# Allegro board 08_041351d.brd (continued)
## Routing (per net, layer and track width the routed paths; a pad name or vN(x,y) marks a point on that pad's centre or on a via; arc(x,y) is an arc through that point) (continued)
PS_MIO06_500_QSPI0_SCLK: length 51.3
  TOP w0.127: U1.A5 v1(37.14,35.39)
  TOP w0.14: v1(60.63,57.64) 60.63,58.66 61.27,59.29 67.74,59.29 68.12,58.91 68.12,58.15 68.62,57.66 U13.B2
  L3_SIGNAL w0.095: v1(37.14,35.39) 37.49,35.39 37.8,35.69 37.8,38.41 40.64,41.26 40.64,45.78 42,47.13 48.97,47.13 48.98,47.12 50.65,47.12 51.18,47.66 54.92,47.66 60.63,53.37 v1(60.63,57.64)
  BOTTOM w0.14: R116.1 v1(60.63,57.64)
PS_MIO07_500_USB_RESET_B: length 32.4
  TOP w0.127: U1.D8 v1(34.74,32.99)
  TOP w0.14: U15.27 v1(22.16,49.4)
  L6_SIGNAL w0.095: v1(22.16,49.4) 22.15,49.38 22.15,40.88 20.25,38.97 20.25,35.67 v1(20.5,35.41)
  L15_SIGNAL w0.095: v1(34.74,32.99) 34.74,32.99 34.34,33.38 26.53,33.38 26.34,33.57 26.34,33.95 26.09,34.21 22.51,34.21 22.27,34.45 22.27,34.73 22.08,34.93 20.99,34.93 v1(20.5,35.41)
  BOTTOM w0.14: R31.2 34.81,33.06 v1(34.74,32.99)
PS_MIO08_500_ETH0_RESETN: length 43.8
  TOP w0.127: U1.D5 v1(34.74,35.39)
  L16_SIGNAL w0.095: v1(16.05,3.66) 16.05,6.14 17.2,8.36 18.98,12.43 20.5,15.09 25.58,20.17 25.58,20.81 27.1,22.33 27.1,29.06 27.49,29.45 27.68,29.45 27.87,29.65 27.87,29.84 29.89,31.85 30.08,31.85 30.28,32.05 30.28,32.24 30.69,32.65 30.88,32.65 31.07,32.85 31.07,33.04 31.49,33.45 32.19,33.45 32.48,33.45 32.8,33.77 32.8,33.93 33.12,34.25 33.28,34.25 33.47,34.45 33.47,34.61 33.79,34.93 34.27,34.93 v1(34.74,35.39)
  BOTTOM w0.14: v1(16.05,3.66) 16.73,4.34 U10.16 ; R32.2 35.12,35 v1(34.74,35.39)
PS_MIO09_500_USB_CLK_PD: length 39.1
  TOP w0.127: v1(36.34,35.39) U1.B5
  TOP w0.14: R27.1 16.98,59.46 Y3.1 16.98,57.98 v1(17.83,57.13)
  L6_SIGNAL w0.095: v1(25.96,45.7) 23.67,47.99 23.67,49.31 24,49.64 24,50.53 21.9,52.63 21.9,54.59 19.36,57.13 v1(17.83,57.13)
  BOTTOM w0.14: v1(25.96,45.7) 33.33,45.7 35.1,43.92 35.87,43.92 36.25,43.54 36.25,42.53 36.76,42.02 36.76,35.8 36.35,35.39 v1(36.34,35.39)
PS_MIO10_500_JX4: length 67.2
  TOP w0.127: U1.E9 v1(33.94,32.19)
  L15_SIGNAL w0.095: v1(33.94,32.19) 34.01,32.19 34.34,31.86 34.34,31.1 35.23,30.21 39.93,30.21 42.22,27.92 45.77,27.92 47.33,26.36 49.81,26.36 51.49,24.68 51.49,20.81 54.73,17.57 55.87,17.57 56.44,17 59.3,17 62.79,13.51 66.92,13.51 67.49,12.94 73.71,12.94 73.97,13.19 73.97,15.09 74.6,15.73 76.19,15.73 76.82,16.36 81.18,16.36 82.75,14.79 v1(83.21,14.79)
  BOTTOM w0.14: v1(83.21,14.79) 83.87,15.45 84.33,15.45 84.66,15.78 84.66,16.04 84.79,16.17 JX4.87
PS_MIO11_500_JX4: length 60.6
  TOP w0.127: U1.C6 v1(35.54,34.59)
  L15_SIGNAL w0.095: v1(35.54,34.59) 35.55,34.59 35.99,35.03 37.26,35.03 39.42,32.87 40.69,32.87 40.95,32.62 49.3,32.62 50.66,31.26 50.66,30.21 51.55,29.32 51.55,27.67 53.07,26.14 53.46,26.14 54.66,24.94 54.66,23.92 58.6,19.98 61.39,19.98 63.36,18.02 66.35,18.02 67.24,18.9 80.76,18.9 v1(82.98,16.68)
  BOTTOM w0.14: v1(82.98,16.68) 82.98,16.3 82.85,16.17 JX4.88
PS_MIO12_500_JX4: length 58.8
  TOP w0.127: U1.D9 v1(34.74,32.19)
  L15_SIGNAL w0.095: v1(34.74,32.19) 34.74,32.1 35.11,31.73 36.48,31.73 36.8,31.41 36.8,31.25 36.99,31.05 37.06,31.05 37.64,30.46 40.57,30.46 42.22,28.81 45.77,28.81 47.42,27.16 49.46,27.16 51.8,24.81 51.8,22.33 53.07,21.06 54.6,21.06 55.42,20.24 55.42,18.59 56.63,17.38 59.43,17.38 62.98,13.82 71.17,13.82 73.39,16.05 75.74,16.05 v1(76.19,16.49)
  BOTTOM w0.14: v1(76.19,16.49) 79.68,16.49 80.16,16.97 JX4.86
PS_MIO13_500_JX4: length 64.6
  TOP w0.127: U1.E8 v1(33.94,32.99)
  L15_SIGNAL w0.095: v1(33.94,32.99) 33.97,32.99 34.34,32.62 38.03,32.62 39.74,30.91 40.75,30.91 41.23,30.43 48.98,30.43 49.2,30.21 49.2,29.76 49.39,29.57 49.84,29.57 50.47,28.94 50.47,27.16 52.44,25.19 52.44,22.58 53.25,21.78 54.9,21.78 56.14,20.54 56.14,18.88 56.93,18.1 59.72,18.1 60.95,16.87 64.48,16.87 65.25,16.11 69.01,16.11 69.78,16.87 81.13,16.87 82.78,15.22 83.64,15.22 v1(84.08,14.79)
  BOTTOM w0.14: v1(84.08,14.79) 84.29,14.57 JX4.91
PS_MIO14_500_JX4: length 67.2
  TOP w0.127: U1.C5 v1(35.54,35.39)
  L15_SIGNAL w0.095: v1(87.38,14.56) 85.9,16.03 85.9,19.29 81.97,23.22 80,23.22 79.49,23.73 57.08,23.73 54.34,26.46 53.2,26.46 51.87,27.79 51.87,29.45 50.98,30.33 50.98,31.46 49.33,33.11 48.68,33.11 48.67,33.13 40.18,33.13 39.17,34.14 39.17,34.4 37.77,35.8 35.87,35.8 35.54,35.46 v1(35.54,35.39)
  BOTTOM w0.14: JX4.93 87.15,13.77 87.38,14 v1(87.38,14.56)
PS_MIO15_500_JX4: length 63.1
  TOP w0.127: U1.C8 v1(35.54,32.99)
  L15_SIGNAL w0.095: v1(35.54,32.99) 35.6,32.99 35.99,33.38 37.77,33.38 39.87,31.29 49.58,31.29 50.03,30.84 50.03,29.89 50.85,29.06 50.85,27.35 52.76,25.44 52.76,22.71 53.33,22.14 55.42,22.14 58.31,19.25 59.08,19.25 61.08,17.25 64.82,17.25 65.58,16.49 68.63,16.49 69.39,17.25 81.21,17.25 82.83,15.63 v1(83.21,15.63)
  BOTTOM w0.14: JX4.85 84.78,16.97 84.63,16.82 84.63,16.44 84.1,15.91 83.49,15.91 v1(83.21,15.63)
PS_MIO16_501_ETH0_TX_CLK: length 43
  TOP w0.127: U1.A19 v1(37.14,23.39)
  L16_SIGNAL w0.095: v1(37.14,23.39) 37.52,23.01 37.52,21.44 36.63,20.56 36.63,20.05 36.37,19.79 36.37,18.02 36.5,17.89 36.88,17.89 37.01,17.76 37.01,17.51 36.88,17.38 36.5,17.38 36.37,17.25 36.37,16.62 36.12,16.36 34.6,16.36 34.47,16.49 33.58,16.49 33.45,16.36 33.45,15.98 33.58,15.86 34.85,15.86 34.98,15.73 34.98,15.22 34.72,14.97 34.72,11.79 35.61,10.9 35.61,8.11 35.36,7.86 33.71,7.86 33.45,8.11 33.45,8.74 33.33,8.87 33.2,8.87 33.07,8.74 33.07,7.6 33.33,7.35 33.45,7.35 33.71,7.09 33.71,6.71 33.45,6.46 31.68,6.46 31.42,6.71 31.42,8.49 31.29,8.62 30.91,8.62 30.79,8.74 30.79,10.01 30.66,10.14 30.41,10.14 30.15,9.89 30.15,8.36 29.39,7.6 v1(29.39,7.35)
  BOTTOM w0.14: v1(29.39,7.35) 29.39,6.97 28.73,6.31 27.69,6.31 27.45,6.07 27.45,5.78 27.27,5.59 26.11,5.59 25.86,5.34 U10.53
PS_MIO17_501_ETH0_TX_D0: length 41.9
  TOP w0.127: U1.E14 v1(33.94,27.39)
  L16_SIGNAL w0.095: v1(26.82,6.84) 26.24,6.84 26.09,6.99 26.09,10.01 26.9,10.83 27.47,10.83 28.16,11.52 28.16,11.55 28.26,11.65 28.26,11.93 28.75,12.43 30.66,12.43 30.79,12.3 30.79,11.28 30.91,11.16 31.17,11.16 31.29,11.28 31.29,12.05 31.42,12.17 31.8,12.17 31.93,12.05 31.93,11.28 32.06,11.16 32.44,11.16 32.56,11.28 32.56,11.54 32.69,11.67 32.95,11.67 33.07,11.54 33.07,11.28 33.2,11.16 33.45,11.16 33.71,11.41 33.71,12.17 33.58,12.3 32.31,12.3 32.18,12.43 32.18,12.68 32.31,12.81 33.2,12.81 33.45,13.06 33.58,13.06 33.71,13.19 33.71,13.7 33.45,13.95 30.91,13.95 30.41,14.46 30.41,14.97 32.99,17.55 33.75,17.55 34.47,18.27 34.47,20.33 34.38,20.41 34.38,26.94 v1(33.94,27.39)
  BOTTOM w0.14: v1(26.82,6.84) 26.82,6.84 U10.50
PS_MIO18_501_ETH0_TX_D1: length 42
  TOP w0.127: U1.B18 v1(36.34,24.19)
  L16_SIGNAL w0.095: v1(36.34,24.19) 36.32,24.19 35.99,23.86 35.99,22.12 35.07,21.2 35.07,20.43 34.98,20.33 34.98,18.27 33.96,17.25 33.07,17.25 31.29,15.48 31.29,14.46 31.55,14.21 33.58,14.21 34.09,13.7 34.09,11.28 33.71,10.9 33.58,10.9 33.33,10.65 33.33,10.27 33.07,10.01 32.31,10.01 32.06,10.27 32.06,10.65 31.8,10.9 30.41,10.9 30.28,11.03 30.28,11.41 29.9,11.79 29.01,11.79 28.84,11.62 28.84,11.27 28.64,11.07 28.08,11.07 27.65,10.65 27.61,10.65 27.56,10.61 27.06,10.61 26.31,9.86 26.31,9.6 26.56,9.35 27.1,9.35 27.36,9.09 27.36,8.65 27.1,8.4 26.55,8.4 26.34,8.19 26.34,7.89 26.55,7.69 27.91,7.69 28.25,7.35 28.25,6.84 28.5,6.59 28.5,4.81 28.25,4.55 27.74,4.55 27.48,4.81 27.48,6.22 27.36,6.34 v1(26.98,6.34)
  BOTTOM w0.14: v1(26.98,6.34) U10.51
PS_MIO19_501_ETH0_TX_D2: length 43.9
  TOP w0.127: U1.D10 v1(34.74,31.39)
  L16_SIGNAL w0.095: v1(34.74,31.39) 35.87,30.26 35.87,29.94 35.87,29.93 35.87,29.65 35.67,29.45 35.45,29.45 35.2,29.19 35.2,27.18 35.45,26.93 35.68,26.93 35.87,26.73 35.87,26.52 36.15,26.25 36.52,26.25 36.76,26.02 36.76,24.87 37.01,24.62 37.26,24.62 37.77,24.11 37.77,21.32 37.39,20.94 37.39,17.25 34.98,14.84 34.98,11.92 35.87,11.03 35.87,7.98 33.58,5.7 33.58,5.44 33.33,5.19 32.69,5.19 32.44,5.44 31.17,5.44 31.04,5.57 31.04,7.98 30.79,8.24 30.53,8.24 29.9,7.6 v1(29.9,7.35)
  BOTTOM w0.14: U10.54 25.87,4.84 26.35,5.32 28.12,5.32 29.75,6.95 29.75,7.2 v1(29.9,7.35)
PS_MIO20_501_ETH0_TX_D3: length 42.6
  TOP w0.127: U1.A17 v1(37.14,24.99)
  L16_SIGNAL w0.095: v1(30.41,7.35) 30.41,6.97 29.14,5.7 29.14,4.43 28.88,4.17 28.25,4.17 27.99,3.92 27.99,3.66 28.25,3.41 33.45,3.41 33.96,3.92 33.96,4.93 34.47,5.44 34.98,5.44 36.12,6.59 36.12,11.16 35.23,12.05 35.23,14.71 37.64,17.13 37.64,20.81 38.28,21.44 38.28,24.11 37.4,24.99 v1(37.14,24.99)
  BOTTOM w0.14: v1(30.41,7.35) 30.26,7.2 30.26,7.08 28.23,5.06 26.59,5.06 25.88,4.34 U10.55
PS_MIO21_501_ETH0_TX_CTL: length 41.8
  TOP w0.127: v1(33.14,27.39) U1.F14
  L16_SIGNAL w0.095: v1(33.14,27.39) 32.8,27.05 32.8,19.54 32.56,19.31 32.56,18.9 32.8,18.67 32.8,18.37 31.68,17.25 30.66,17.25 30.53,17.13 30.53,16.11 29.26,14.84 27.74,14.84 27.61,14.71 27.61,14.33 27.74,14.21 30.28,14.21 30.79,13.7 33.07,13.7 33.2,13.57 33.2,13.32 33.07,13.19 31.93,13.19 31.8,13.06 31.8,12.68 31.68,12.55 31.04,12.55 30.91,12.68 30.91,13.06 30.79,13.19 28.37,13.19 28.25,13.06 28.25,12.43 27.99,12.17 27.99,11.7 27.94,11.64 27.94,11.61 27.56,11.23 26.41,11.23 25.83,10.65 25.83,5.32 v1(26.72,4.43)
  BOTTOM w0.14: U10.56 26.14,3.84 v1(26.72,4.43)
PS_MIO22_501_ETH0_RX_CLK: length 42.9
  TOP w0.127: U1.B17 35.94,25.38 36.33,24.99 v1(36.34,24.99)
  L16_SIGNAL w0.095: v1(27.01,10.01) 27.01,10.09 27.27,10.35 27.7,10.35 28.19,10.85 28.37,10.85 28.5,10.72 28.5,10.4 28.63,10.27 29.01,10.27 29.14,10.4 29.14,11.03 29.26,11.16 29.52,11.16 29.64,11.03 29.64,10.4 29.77,10.27 30.02,10.27 30.28,10.52 31.04,10.52 31.17,10.4 31.17,9.13 31.29,9 31.68,9 31.8,8.87 31.8,7.73 32.06,7.47 32.56,7.47 32.82,7.73 32.82,9.13 33.07,9.38 33.45,9.38 33.71,9.13 33.71,8.49 34.09,8.11 35.1,8.11 35.36,8.36 35.36,10.52 35.23,10.65 34.98,10.65 34.85,10.52 34.85,9.89 34.72,9.76 34.47,9.76 34.34,9.89 34.34,13.95 33.71,14.59 32.28,14.59 32.27,14.57 31.82,14.57 31.68,14.71 31.68,15.22 33.38,16.93 34.4,16.93 35.99,18.52 35.99,20.33 35.91,20.41 35.91,21.23 36.76,22.08 36.76,24.37 36.34,24.79 v1(36.34,24.99)
  BOTTOM w0.14: U10.46 25.93,8.84 26.87,9.78 26.87,9.78 27.01,9.92 v1(27.01,10.01)
PS_MIO23_501_ETH0_RX_D0: length 42.3
  TOP w0.127: U1.D11 v1(34.74,29.79)
  L16_SIGNAL w0.095: v1(26.85,11.79) 26.85,13.57 26.37,14.05 26.37,14.21 26.43,14.27 26.43,14.6 26.23,14.8 26.21,14.8 26.21,15.73 26.34,15.86 26.72,15.86 26.95,16.09 27.27,16.09 27.51,16.32 27.51,16.64 28.63,17.76 29.01,17.76 29.77,18.52 30.28,18.52 30.41,18.65 30.41,19.29 30.28,19.41 29.9,19.41 29.77,19.54 29.77,20.05 29.9,20.17 31.17,20.17 31.29,20.3 31.29,21.06 31.17,21.19 29.64,21.19 29.52,21.32 29.52,26.91 29.64,27.03 30.15,27.03 30.28,26.91 30.28,21.95 30.41,21.83 31.04,21.83 31.17,21.95 31.17,28.3 31.51,28.65 31.68,28.65 31.87,28.85 31.87,29.01 32.19,29.33 33.21,29.33 33.71,29.83 34.7,29.83 v1(34.74,29.79)
  BOTTOM w0.14: U10.44 25.92,9.84 26.21,10.14 26.21,10.4 26.85,11.03 v1(26.85,11.79)
PS_MIO24_501_ETH0_RX_D1: length 42
  TOP w0.127: U1.A16 v1(37.14,25.79)
  L16_SIGNAL w0.095: v1(35.87,14.21) 37.9,16.24 37.9,20.56 38.66,21.32 38.66,24.24 37.14,25.76 v1(37.14,25.79)
  BOTTOM w0.14: v1(35.87,14.21) 35.87,13.82 35.74,13.7 33.83,13.7 33.58,13.95 33.58,14.46 33.83,14.71 34.98,14.71 35.23,14.97 35.23,15.86 34.98,16.11 34.47,16.11 33.96,16.62 32.06,16.62 31.55,16.11 28.37,16.11 28.18,16.3 27.54,16.3 27.29,16.05 27.29,15.98 27.04,15.73 26.74,15.73 26.49,15.48 26.49,14.59 26.74,14.33 27.48,14.33 27.74,14.59 27.74,15.35 27.99,15.6 28.37,15.6 28.63,15.35 28.63,13.57 28.37,13.32 27.48,13.32 27.23,13.06 27.23,10.9 26.6,10.27 26.6,9.89 26.05,9.34 U10.45
PS_MIO25_501_ETH0_RX_D2: length 43.9
  TOP w0.127: v1(33.14,26.59) U1.F15
  L16_SIGNAL w0.095: v1(33.14,26.59) 33.58,26.14 33.58,20.05 33.33,19.79 33.33,18.52 29.9,15.09 v1(29.9,14.59)
  BOTTOM w0.14: U10.47 26.07,8.34 27.38,9.65 27.68,9.65 28.53,10.5 29.04,10.5 30.02,9.51 30.02,8.49 30.28,8.24 31.17,8.24 31.55,7.86 32.64,7.86 32.89,8.11 32.89,8.8 32.56,9.13 31.04,9.13 30.41,9.76 30.41,10.27 29.9,10.78 29.46,10.78 29.14,11.1 29.14,14.71 29.77,15.35 30.91,15.35 31.77,14.5 31.77,13.57 32.02,13.32 32.31,13.32 32.56,13.06 32.56,12.55 32.31,12.3 31.17,12.3 30.91,12.55 30.91,13.32 30.66,13.57 30.15,13.57 29.9,13.82 v1(29.9,14.59)
PS_MIO26_501_ETH0_RX_D3: length 41.9
  TOP w0.127: U1.A15 v1(37.14,26.59)
  L16_SIGNAL w0.095: v1(24.82,7.84) 24.82,4.81 25.45,4.17 25.45,2.9 25.79,2.56 33.62,2.56 34.98,3.92 34.98,5.06 36.37,6.46 36.37,14.08 38.41,16.11 38.41,17.89 38.79,18.27 38.79,20.68 39.04,20.94 39.04,24.68 v1(37.14,26.59)
  BOTTOM w0.14: U10.48 v1(24.82,7.84)
PS_MIO27_501_ETH0_RX_CTL: length 41.8
  TOP w0.127: U1.D13 v1(34.74,28.19)
  L16_SIGNAL w0.095: v1(34.74,28.19) 34.34,28.58 34.34,29.32 34.09,29.57 33.83,29.57 33.58,29.32 33.58,27.92 33.45,27.79 32.82,27.79 32.69,27.92 32.69,28.3 32.67,28.32 32.67,28.33 32.48,28.53 32.47,28.53 32.44,28.56 32.18,28.56 31.93,28.3 31.93,21.44 32.18,21.19 32.18,20.3 31.8,19.92 31.8,17.89 31.55,17.63 29.9,17.63 29.64,17.38 29.01,17.38 28.88,17.25 28.88,16.49 29.01,16.36 29.64,16.36 29.77,16.24 29.77,16.11 29.64,15.98 27.48,15.98 27.36,15.87 27.24,15.87 27.23,15.86 27.23,15.6 27.36,15.48 29.14,15.48 29.26,15.35 29.26,15.22 29.14,15.09 27.1,15.09 26.98,14.97 26.98,13.95 27.1,13.82 30.02,13.82 30.15,13.7 30.15,13.57 30.02,13.44 27.52,13.44 27.27,13.19 27.27,11.69 27.03,11.45 26.68,11.45 v1(26.34,11.79)
  BOTTOM w0.14: v1(26.34,11.79) 26.34,11.53 25.59,10.78 U10.43
PS_MIO28_501_USB0_D4: length 38.6
  TOP w0.127: U1.C16 v1(35.54,25.79)
  TOP w0.14: v1(26.85,54.97) 26.07,54.19 U15.7
  L6_SIGNAL w0.095: v1(35.54,25.79) 35.07,26.25 35.07,26.73 34.88,26.93 33.12,26.93 32.8,27.25 32.8,27.41 32.48,27.73 32.32,27.73 31.87,28.17 31.87,28.33 31.68,28.53 31.52,28.53 31.2,28.85 31.2,29.04 30.78,29.45 30.59,29.45 30.4,29.65 30.4,29.84 29.37,30.86 29.37,31.62 29.14,31.86 29.14,41.26 28.75,41.64 28.75,48.77 26.98,50.55 26.98,52.08 26.51,52.55 26.51,53.41 26.42,53.5 26.42,53.93 26.65,54.16 27.61,54.16 27.79,54.33 27.79,54.47 27.64,54.62 26.95,54.62 26.87,54.69 26.87,54.95 v1(26.85,54.97)
PS_MIO29_501_USB0_DIR: length 32.9
  TOP w0.127: U1.C13 v1(35.54,28.19)
  TOP w0.14: U15.31 24.16,49.53 v1(24.31,49.38)
  BOTTOM w0.14: v1(24.31,49.38) 24.82,49.38 25.2,49 25.2,45.7 24.69,45.19 24.69,44.3 25.2,43.8 25.2,39.1 25.57,38.72 25.57,38.44 25.79,38.23 26.07,38.23 26.37,37.92 26.37,37.64 26.59,37.43 26.87,37.43 27.17,37.12 27.17,36.84 27.39,36.63 27.67,36.63 27.97,36.32 27.97,36.04 28.19,35.83 28.47,35.83 29.26,35.03 29.26,28.3 29.77,27.79 35.1,27.79 35.5,28.19 v1(35.54,28.19)
PS_MIO30_501_USB0_STP: length 34.7
  TOP w0.127: U1.C15 v1(35.54,26.59)
  TOP w0.14: U15.29 v1(23.16,49.39)
  BOTTOM w0.14: v1(23.16,49.39) 23.17,49.38 23.17,45.7 22.79,45.32 22.79,40.49 24.33,38.95 24.49,38.95 24.7,38.74 24.7,38.52 24.99,38.23 25.21,38.23 25.5,37.94 25.5,37.72 25.79,37.43 26.01,37.43 26.3,37.14 26.3,36.92 26.59,36.63 26.81,36.63 27.1,36.34 27.1,36.12 27.39,35.83 27.61,35.83 27.9,35.54 27.9,35.32 28.19,35.03 28.25,35.03 28.88,34.4 28.88,26.78 29.43,26.23 35.19,26.23 35.54,26.57 v1(35.54,26.59)
PS_MIO31_501_USB0_NXT: length 35.3
  TOP w0.127: U1.E16 v1(33.94,25.79)
  TOP w0.14: U15.2 v1(25.94,51.69)
  L6_SIGNAL w0.095: v1(25.94,51.69) 26.47,51.16 26.47,49.38 26.8,49.05 26.8,48.83 26.88,48.75 27.48,48.75 27.61,48.62 27.61,48.24 27.48,48.11 26.85,48.11 26.8,48.06 26.8,47.7 26.89,47.61 27.48,47.61 27.61,47.48 27.61,47.1 27.48,46.97 26.98,46.97 26.8,46.79 26.8,44.61 27.7,43.71 27.7,39.14 28,38.84 28,35.25 28.48,34.77 28.48,34.41 28,33.93 28,32.05 28.19,31.85 28.35,31.85 28.66,31.54 28.66,31.51 28.91,31.26 28.91,30.33 29.37,29.87 29.37,29.56 29.6,29.33 29.6,28.85 29.79,28.65 30.08,28.65 30.4,28.33 30.4,28.05 30.59,27.85 30.88,27.85 31.2,27.53 31.2,27.25 31.39,27.05 31.68,27.05 32,26.73 32,26.45 32.2,26.25 32.48,26.25 32.8,25.93 32.8,25.65 32.99,25.45 33.28,25.45 33.61,25.79 v1(33.94,25.79)
PS_MIO32_501_USB0_D0: length 38.5
  TOP w0.127: U1.A14 v1(37.14,27.39)
  TOP w0.14: v1(26.85,52.69) 26.35,52.19 U15.3
  L6_SIGNAL w0.095: v1(37.14,27.39) 36.8,27.05 35.19,27.05 35.07,27.16 35.07,27.53 34.75,27.85 32.99,27.85 32.8,28.05 32.8,28.33 32.48,28.65 32.2,28.65 32,28.85 32,29.13 31.68,29.45 31.39,29.45 31.2,29.65 31.2,29.93 30.08,31.05 29.79,31.05 29.6,31.25 29.6,31.71 29.37,31.93 29.37,38.82 29.6,39.05 29.6,39.44 30.15,39.99 30.15,41.09 29.6,41.64 29.6,45.08 29.54,45.14 29.54,48.14 30.13,48.72 30.13,49.99 29.92,50.2 29.92,50.6 29.8,50.73 29.57,50.73 28.63,49.79 28.14,49.79 27.84,50.1 27.84,51.82 26.98,52.69 v1(26.85,52.69)
PS_MIO33_501_USB0_D1: length 36.3
  TOP w0.127: U1.D15 v1(34.74,26.59)
  TOP w0.14: U15.4 v1(25.96,52.69)
  L6_SIGNAL w0.095: v1(25.96,52.69) 25.96,52.44 26.72,51.67 26.72,50.15 27.99,48.88 27.99,46.49 27.9,46.4 27.2,46.4 27.1,46.3 27.1,46.11 27.2,46.02 27.9,46.02 27.99,45.92 27.99,45.73 27.9,45.64 27.2,45.64 27.1,45.54 27.1,45.35 27.2,45.26 27.9,45.26 27.99,45.16 27.99,39.73 28.88,38.84 28.88,31.6 29.14,31.35 29.14,30.59 29.6,30.13 29.6,29.65 29.79,29.45 30.08,29.45 30.4,29.13 30.4,28.85 30.59,28.65 30.88,28.65 31.2,28.33 31.2,28.05 31.39,27.85 31.68,27.85 32,27.53 32,27.25 32.2,27.05 32.48,27.05 32.8,26.73 32.8,26.45 32.99,26.25 33.47,26.25 33.58,26.14 34.29,26.14 v1(34.74,26.59)
PS_MIO34_501_USB0_D2: length 38.6
  TOP w0.127: U1.A12 v1(37.14,28.99)
  TOP w0.14: v1(26.85,53.7) 26.34,53.19 U15.5
  L6_SIGNAL w0.095: v1(37.14,28.99) 36.8,28.65 32.99,28.65 32.67,28.97 32.67,29.13 32.48,29.33 32.32,29.33 31.87,29.77 31.87,29.93 31.68,30.13 31.52,30.13 30.27,31.37 30.27,31.53 30.08,31.73 29.92,31.73 29.6,32.05 29.6,38.73 29.85,38.98 29.85,39.27 30.41,39.83 30.41,41.38 29.9,41.89 29.9,47.91 30.41,48.42 30.41,50.07 30.15,50.32 30.15,52.1 30.02,52.23 29.8,52.23 29.67,52.1 29.67,51.16 29.49,50.99 29.36,50.99 29.21,51.14 29.21,51.45 29.12,51.54 29.08,51.54 28.83,51.8 28.25,51.8 27.36,52.69 27.36,52.94 26.85,53.45 v1(26.85,53.7)
PS_MIO35_501_USB0_D3: length 34.8
  TOP w0.127: v1(33.14,28.99) U1.F12
  TOP w0.14: U15.6 v1(25.95,53.69)
  L6_SIGNAL w0.095: v1(33.14,28.99) 32.8,29.33 32.8,29.81 32.48,30.13 32.32,30.13 31.2,31.25 31.2,31.41 30.88,31.73 30.72,31.73 30.4,32.05 30.4,38.73 30.65,38.98 30.65,50.34 30.85,50.54 30.85,50.82 30.53,51.14 30.53,53.45 29.2,54.78 27.8,54.78 27.26,55.33 25.63,55.33 25.45,55.15 25.45,54.19 v1(25.95,53.69)
PS_MIO36_501_USB0_CLK: length 32.8
  TOP w0.127: U1.A11 v1(37.14,29.79)
  TOP w0.14: U15.1 25.55,51.19 v1(25.96,50.78)
  BOTTOM w0.14: v1(37.14,29.79) 37.14,29.83 37.77,30.46 37.77,39.22 39.17,40.62 39.17,43.54 38.15,44.56 35.74,44.56 34.85,45.45 34.85,46.59 33.83,47.61 29.14,47.61 v1(25.96,50.78)
PS_MIO37_501_USB0_D5: length 34.3
  TOP w0.127: U1.A10 v1(37.14,31.39)
  TOP w0.14: U15.9 24.66,55.83 v1(24.94,56.12)
  L6_SIGNAL w0.095: v1(24.94,56.12) 27.09,56.12 28.11,55.1 29.29,55.1 30.79,53.6 30.79,51.42 31.47,50.74 31.47,49.41 31.29,49.24 31.29,46.84 31.68,46.46 v1(31.68,46.21)
  L12_SIGNAL w0.095: v1(31.68,46.21) 31.68,45.45 32.95,44.18 32.95,41.89 35.36,39.48 36.25,39.48 36.8,38.93 36.8,37.65 36.99,37.45 37.28,37.45 37.52,37.21 37.52,31.77 v1(37.14,31.39)
PS_MIO38_501_USB0_D6: length 38.3
  TOP w0.127: U1.E13 v1(33.94,28.19)
  TOP w0.14: U15.10 24.16,55.97 v1(24.31,56.12)
  L6_SIGNAL w0.095: v1(24.31,56.12) 24.75,56.56 28.18,56.56 31.04,53.7 31.04,51.67 31.8,50.91 31.8,50.4 32.31,49.89 32.31,46.94 32.56,46.7 32.56,44.55 v1(31.93,43.92)
  BOTTOM w0.14: v1(33.94,28.19) 33.94,28.2 33.57,28.56 33.57,30.34 33.2,30.72 31.55,30.72 31.17,31.1 31.17,43.16 v1(31.93,43.92)
PS_MIO39_501_USB0_D7: length 39.3
  TOP w0.127: U1.C18 v1(35.54,24.19)
  TOP w0.14: v1(22.91,56.12) 22.66,55.87 U15.13
  L6_SIGNAL w0.095: v1(22.91,56.12) 25.6,52.05 25.6,49.51 26.58,46.97 26.58,43.42 27.2,38.46 27.2,32.05 27.52,31.73 27.68,31.73 27.87,31.53 27.87,31.47 27.99,31.35 27.99,31.22 29.14,29.45 29.26,29.32 29.26,28.38 29.92,27.73 30.08,27.73 30.4,27.41 30.4,27.25 30.72,26.93 30.88,26.93 31.2,26.61 31.2,26.45 31.52,26.13 31.68,26.13 32,25.81 32,25.65 32.32,25.33 32.48,25.33 32.8,25.01 32.8,24.85 32.99,24.65 33.66,24.53 34.88,24.53 35.14,24.26 v1(35.54,24.19)
PS_MIO40_501_SD0_CLK: length 33.1
  TOP w0.127: U1.D14 v1(34.74,27.39)
  TOP w0.14: v1(9.7,20.05) 8.05,18.39 U11.9
  L7_SIGNAL w0.095: v1(34.74,27.39) 34.74,27.4 34.34,27.79 20.12,27.79 19.61,27.29 16.94,27.29 v1(9.7,20.05)
PS_MIO41_501_SD0_CMD: length 36.5
  TOP w0.127: v1(35.54,24.99) 35.53,24.99 35.14,25.38 U1.C17
  TOP w0.14: U11.4 10.44,14.84 10.59,14.69 10.59,14.46 10.85,14.21 v1(11.23,14.21)
  L4_SIGNAL w0.095: v1(33.83,15.48) 33.83,15.03 32.44,13.63 27.04,13.63 26.6,14.07 12,14.07 11.86,14.21 v1(11.23,14.21)
  L15_SIGNAL w0.095: v1(33.83,15.48) 34.22,15.86 34.22,17.25 34.98,18.02 35.02,18.02 35.02,18.66 35.1,18.75 35.1,24.62 35.47,24.99 v1(35.54,24.99)
PS_MIO42_501_SD0_DATA0: length 41
  TOP w0.127: U1.E12 v1(33.94,28.99)
  TOP w0.14: U11.6 v1(9.8,16.36)
  L4_SIGNAL w0.095: v1(33.33,15.48) 32.88,15.92 32.18,15.92 30.51,14.25 27.32,14.25 26.4,15.16 25.77,15.16 25.01,15.92 17.58,15.92 17.01,15.35 12.31,15.35 11.29,16.36 v1(9.8,16.36)
  L15_SIGNAL w0.095: v1(33.33,15.48) 33.96,16.11 33.96,17.51 34.34,17.89 34.34,28.56 33.94,28.96 v1(33.94,28.99)
PS_MIO43_501_SD0_DATA1: length 46.4
  TOP w0.127: U1.A9 v1(37.14,32.19)
  TOP w0.14: v1(9.7,17.76) 9.05,17.11 U11.7
  L16_SIGNAL w0.095: v1(37.14,32.19) 37.14,32.24 36.76,32.62 36.76,34.02 36.52,34.25 36.19,34.25 36,34.45 36,34.73 35.68,35.05 35.39,35.05 35.2,35.25 35.2,35.58 34.98,35.8 33.71,35.8 33.47,35.56 33.47,35.25 33.28,35.05 32.99,35.05 32.67,34.73 32.67,34.45 32.37,34.14 20.12,34.14 19.61,33.64 14.53,33.64 13.39,32.49 13.39,21.95 9.7,18.27 v1(9.7,17.76)
PS_MIO44_501_SD0_DATA2: length 40.2
  TOP w0.127: v1(33.14,28.19) U1.F13
  TOP w0.14: v1(10.59,13.06) 10.32,13.34 U11.1
  L4_SIGNAL w0.095: v1(10.59,13.06) 10.34,13.32 10.34,14.21 10.78,14.65 16.82,14.65 17.64,15.48 24.88,15.48 25.52,14.84 26.21,14.84 27.1,13.95 30.6,13.95 32.12,15.48 v1(32.69,15.48)
  L15_SIGNAL w0.095: v1(33.14,28.19) 33.14,28.11 33.58,27.67 33.58,18.75 33.49,18.66 33.49,18.38 33.58,18.3 33.58,16.36 v1(32.69,15.48)
PS_MIO45_501_SD0_DATA3: length 38.7
  TOP w0.127: v1(36.34,26.59) U1.B15
  TOP w0.14: v1(10.97,13.7) 10.34,14.34 U11.3
  L4_SIGNAL w0.095: v1(34.47,15.48) 34.47,15.03 32.75,13.32 22.53,13.32 22.15,13.7 v1(10.97,13.7)
  L15_SIGNAL w0.095: v1(36.34,26.59) 36.34,26.49 35.91,26.06 35.91,18.06 35.23,17.38 35.23,16.24 v1(34.47,15.48)
PS_MIO46_501_JX4: length 60.9
  TOP w0.127: U1.D16 v1(34.74,25.79)
  TOP w0.14: R37.2 v1(40.06,24.24)
  L15_SIGNAL w0.095: v1(80.19,14.59) 78.79,13.19 78.28,13.19 76.57,11.47 58.79,11.47 58.28,11.98 58.28,15.16 57.96,15.48 54.22,15.48 50.22,19.48 50.22,23.73 49.96,23.98 41.96,23.98 41.71,24.24 v1(40.06,24.24) 37.26,27.03 36.25,27.03 35.87,26.66 35.87,26.45 35.68,26.25 35.21,26.25 34.75,25.79 v1(34.74,25.79)
  BOTTOM w0.14: v1(80.19,14.59) 80.25,14.59 80.27,14.57 JX4.92
PS_MIO47_501_JX4: length 59.6
  TOP w0.127: v1(36.34,27.39) U1.B14
  TOP w0.305: R26.1 v1(40.82,27.41)
  L15_SIGNAL w0.095: v1(78.67,14.59) 78.67,13.88 77.97,13.19 77.01,13.19 75.68,11.86 59.11,11.86 58.6,12.36 58.6,15.28 58.09,15.79 54.34,15.79 50.53,19.6 50.53,23.86 50.03,24.37 44.38,24.37 43.87,24.87 42.72,24.87 41.07,26.52 41.07,27.16 v1(40.82,27.41) 40.44,27.79 36.76,27.79 36.35,27.39 v1(36.34,27.39)
  BOTTOM w0.14: JX4.94 79.48,13.77 v1(78.67,14.59)
PS_MIO48_501_JX4: length 64.5
  TOP w0.127: v1(36.34,28.99) U1.B12
  L15_SIGNAL w0.095: v1(36.34,28.99) 36.66,28.99 36.99,29.33 40.17,29.33 42.4,27.1 46.08,27.1 47.61,25.57 49.71,25.57 51.17,24.11 51.17,20.62 55.17,16.62 59.17,16.62 63.26,12.53 75.28,12.53 76.51,13.76 76.51,15.54 77.01,16.05 81.07,16.05 83.81,13.3 83.81,11.98 v1(84.38,11.41)
  BOTTOM w0.14: v1(84.38,11.41) 84.42,11.37 JX4.99
PS_MIO49_501_JX4: length 64.4
  TOP w0.127: U1.C12 v1(35.54,28.99)
  L15_SIGNAL w0.095: v1(82.98,12.2) 83.42,12.63 83.42,13.24 80.93,15.73 77.14,15.73 76.82,15.41 76.82,13.63 75.36,12.17 61.84,12.17 61.01,13 61.01,14.27 58.98,16.3 55.04,16.3 50.85,20.49 50.85,23.98 50.09,24.75 46.88,24.75 45.23,26.4 42.47,26.4 40.31,28.56 35.99,28.56 35.56,28.99 v1(35.54,28.99)
  BOTTOM w0.14: JX4.98 81.55,12.17 82.96,12.17 v1(82.98,12.2)
PS_MIO50_501_SD0_CD: length 81.3
  TOP w0.127: v1(36.34,28.19) U1.B13
  TOP w0.14: U5.8 78.08,58.47 77.9,58.66 v1(77.9,59.16)
  L16_SIGNAL w0.095: v1(77.9,59.16) 77.24,59.16 77.15,59.25 74.94,59.25 71.3,55.61 64.82,55.61 60,50.78 50.98,50.78 49.29,49.09 49.29,35.39 49.33,35.35 49.33,32.75 49.2,32.62 49.2,20.98 48.95,20.72 42.17,20.72 41.01,21.89 41.01,24.17 40.44,24.75 40.06,24.75 38.53,26.27 38.53,27.67 37.55,28.65 36.85,28.65 36.39,28.19 v1(36.34,28.19)
PS_MIO51_501_JX4: length 59.3
  TOP w0.127: v1(36.34,32.19) U1.B9
  L15_SIGNAL w0.095: v1(36.34,32.19) 36.66,32.19 36.99,31.85 38.26,31.85 39.42,30.68 40.66,30.68 41.77,29.57 45.9,29.57 46.72,28.75 49.84,28.75 50.09,28.49 50.09,27.03 52.12,25 52.12,22.46 53.16,21.42 54.75,21.42 55.78,20.39 55.78,18.74 56.78,17.74 59.57,17.74 60.82,16.49 64.31,16.49 65.08,15.73 69.14,15.73 69.9,16.49 v1(75.43,16.49)
  BOTTOM w0.14: v1(75.43,16.49) 75.44,16.49 76.79,15.15 76.79,13.47 78.88,11.37 JX4.100
PS_MIO52_501_ETH0_MDC: length 41.7
  TOP w0.127: U1.C10 v1(35.54,31.39)
  L4_SIGNAL w0.095: v1(25.96,3.28) 25.96,2.65 25.83,2.52 21.9,2.52 v1(21.64,2.27)
  L16_SIGNAL w0.095: v1(25.96,3.28) 25.96,4.05 25.2,4.81 25.2,10.78 25.27,10.85 25.27,15.93 28.12,18.78 28.12,20.81 28.82,21.51 28.82,27.55 29.92,28.65 30.08,28.65 30.4,28.97 30.4,29.13 30.72,29.45 30.88,29.45 31.2,29.77 31.2,29.93 31.39,30.13 31.47,30.13 31.93,30.59 33.83,30.59 34.34,31.1 34.34,31.48 34.6,31.73 35.19,31.73 v1(35.54,31.39)
  BOTTOM w0.14: v1(21.64,2.27) 21.89,2.52 U10.7
PS_MIO53_501_ETH0_MDIO: length 43.1
  TOP w0.127: U1.C11 v1(35.54,29.79)
  L4_SIGNAL w0.095: v1(21.01,2.27) 21.64,2.9 24.69,2.9 25.58,3.79 v1(26.72,3.79)
  L16_SIGNAL w0.095: v1(35.54,29.79) 35.54,30.16 35.1,30.59 34.69,30.59 34.44,30.33 32.95,30.33 32.44,30.32 32.24,30.13 32.2,30.13 32,29.93 32,29.77 31.68,29.45 31.52,29.45 31.2,29.13 31.2,28.97 30.88,28.65 30.72,28.65 30.4,28.33 30.4,28.17 30.08,27.85 29.92,27.85 29.26,27.2 29.26,20.43 28.63,19.79 28.63,18.65 25.58,15.6 25.58,12.17 25.49,11.67 25.49,10.69 25.45,10.65 25.45,5.06 v1(26.72,3.79)
  BOTTOM w0.14: v1(21.01,2.27) 21.38,2.64 21.39,2.64 U10.8 ; R11.2 26.98,4.05 v1(26.72,3.79)
PWR_ENABLE: length 96
  TOP w0.14: R56.2 30.02,56.31 30.02,56.88 30.41,57.26 31.55,57.26 v1(31.93,57.64) ; U18.15 23.11,4.04 23.48,3.66 24.31,3.66 v1(24.82,4.17)
  L16_SIGNAL w0.095: v1(24.82,4.17) 24.06,3.41 16.94,3.41 16.69,3.16 15.93,3.16 15.55,3.54 15.55,8.62 15.04,9.13 14.02,9.13 12.75,10.4 10.85,10.4 9.96,11.28 9.2,11.28 8.56,11.92 8.56,24.87 10.47,26.78 10.47,49.13 18.34,57 20.37,57 20.88,57.51 25.2,57.51 25.9,58.21 28.94,58.21 29.39,58.66 31.42,58.66 31.93,58.15 v1(31.93,57.64)
  BOTTOM w0.14: JX1.5 32.73,56.84 v1(31.93,57.64)
PWR_GD: length 104.8
  TOP w0.254: v2(42.03,53.89) 41.58,53.44 U9.7
  TOP w0.305: U19.5 82.18,8.02 v1(82.6,7.6) ; R306.1 v1(83.87,7.6)
  TOP w0.381: U20.5 91.96,8.02 v2(92.25,7.73)
  L12_SIGNAL w0.305: v1(82.6,7.6) v1(83.87,7.6) 84.38,7.09 89.14,7.09 89.78,7.73 v2(92.25,7.73) 93.02,8.49 93.02,10.52 92.51,11.03 92.51,12.17 91.11,13.57 91.11,33.32 88.51,35.92 87.45,35.92 86.16,37.22 86.16,45.83 85.14,46.84 75.87,46.84 75.24,47.48 75.24,48.62 69.14,54.72 42.85,54.72 v2(42.03,53.89)
PWR_GD_1.35V: length 80.5
  TOP w0.127: U1.C7 v1(35.54,33.79)
  TOP w0.305: U4.12 70.14,4.48 70.2,4.42 70.71,4.42 v2(70.96,4.17)
  TOP w0.406: v2(41.2,16.87) 41.2,15.86 41.77,15.28 41.77,12.11 40.95,11.28 40.95,6.71 SW1.1A ; R22.1 71.35,4.55 v2(70.96,4.17)
  TOP w0.508: v1(41.07,4.43) 40.69,4.43 v1(40.57,4.55) 40.57,5.19 40.06,5.7 SW1.1A SW1.1B
  L4_SIGNAL w0.203: v1(35.54,33.79) 35.93,34.18 38.19,34.18 v1(38.53,34.53)
  L4_SIGNAL w0.406: v2(70.96,4.17) 69.9,4.17 68.51,2.78 65.58,2.78 63.88,1.07 61.7,1.07 60.5,2.27 56.06,2.27 55.04,1.25 53.07,1.25 52.31,2.01 45.9,2.01 44.5,3.41 42.09,3.41 v1(41.07,4.43) 40.69,4.43 v1(40.57,4.55)
  BOTTOM w0.406: v2(41.2,16.87) 41.2,25.64 38.91,27.92 38.91,33.26 38.53,33.64 v1(38.53,34.53) ; C34.1 42,3.5 v1(41.07,4.43)
RX_EXT_LO: length 16.3
  TOP w0.127: v1(65.81,24.67) 65.81,25.08 U17.G1
  L16_SIGNAL w0.095: W1.1 72.95,16.62 70.66,16.62 69.55,17.73 69.55,18.49 65.81,22.23 v1(65.81,24.67)
RX_VCO_LDO_OUT: length 8.3
  TOP w0.127: U17.G3 v1(66,26.49) ; U17.G2 v1(66,25.69)
  TOP w0.14: 62.47,21.83 v1(62.47,22.38) C13.2
  L16_SIGNAL w0.095: v1(62.47,22.38) 62.47,23.03 63.49,24.05 64.35,24.05 v1(66,25.69) v1(66,26.49)
RXA_N: length 6.2
  TOP w0.267: C8.2 74.53,23.81 74.48,23.69 73.78,23.38 73.72,23.36 73.69,23.34 arc(73.61,23.3) 73.53,23.28 arc(73.48,23.27) 73.43,23.27 73.13,23.27 arc(72.74,23.34) 72.42,23.56 70.53,25.45 69.78,25.78 arc(69.67,25.93) U17.M2
RXA_P: length 6.2
  TOP w0.267: U17.M1 69.82,25.2 70.23,25.01 72.05,23.19 arc(72.54,22.86) 73.13,22.75 73.43,22.75 arc(73.7,22.78) 73.96,22.89 74.14,22.97 arc(74.49,23.06) C9.2
RXB_N: length 6.2
  TOP w0.267: C85.2 66.34,20.66 66.07,20.94 arc(65.95,21.1) 65.9,21.29 65.9,22.94 arc(65.95,23.21) 66.11,23.44 arc(66.26,23.54) 66.45,23.58 67.04,23.58 arc(67.29,23.68) 67.39,23.92 67.39,24.07 arc(67.34,24.26) 67.2,24.41 67.08,24.49 arc(66.98,24.61) 66.92,24.75 arc(66.97,25.07) U17.J1
RXB_P: length 6.3
  TOP w0.267: C90.2 66.4,19.87 65.7,20.57 arc(65.48,20.88) 65.38,21.25 arc(65.38,21.26) 65.38,21.27 65.38,22.94 arc(65.47,23.41) 65.74,23.81 66.19,24.26 arc(66.34,24.44) 66.4,24.67 U17.H1
S_IN_N: length 55.9
  L16_SIGNAL w0.089: v1(24.33,2.01) 24.54,2.23 24.54,2.65 24.29,2.9 20.99,2.9 20.4,2.31 15.65,2.31 11.12,6.84 9.34,6.84 8.69,7.49 6.74,7.49 v1(6.53,7.28)
  BOTTOM w0.089: v1(24.33,2.01) 24.53,2.22 24.53,2.46 24.39,2.6 U10.2 ; JP2.3 3.74,34.6 3.74,33.76 3.61,33.64 1.96,33.64 0.9,32.58 0.9,23.77 1.58,23.1 1.58,9.71 2.92,8.36 4.62,8.36 5.48,7.51 6.29,7.51 v1(6.53,7.28)
S_IN_P: length 55.9
  L16_SIGNAL w0.089: v1(25.01,2.01) 24.8,2.23 24.8,2.75 24.4,3.16 20.88,3.16 20.29,2.57 15.76,2.57 11.23,7.09 9.45,7.09 8.8,7.75 6.74,7.75 v1(6.53,7.96)
  BOTTOM w0.089: U10.1 24.89,2.6 24.75,2.46 24.75,2.28 v1(25.01,2.01) ; JP1.3 3.74,32.42 3.74,33.26 3.57,33.42 3.12,33.42 2.83,33.13 2.72,33.13 2.43,33.42 2.05,33.42 1.11,32.49 1.11,23.86 1.79,23.19 1.79,9.8 3.01,8.58 4.71,8.58 5.56,7.73 6.29,7.73 v1(6.53,7.96)
S_OUT_N: length 41.6
  L6_SIGNAL w0.089: v1(17.96,32.49) 17.65,32.19 17.47,32.19 17.2,31.91 17.2,29.45 18.09,28.56 18.09,24.49 18.59,23.98 19.23,23.98 19.7,23.51 19.7,14.39 21.77,12.32 21.77,10.88 20.88,9.99 20.88,7.2 18.85,5.17 18.85,3.54 19.36,3.03 22.53,3.03 23.04,2.52 23.04,2.01 v1(22.79,1.76)
  BOTTOM w0.089: v1(22.79,1.76) 23.03,2.01 23.03,2.46 22.89,2.6 U10.5 ; v1(17.96,32.49) 17.96,32.24 17.83,32.11 17.45,32.11 17.15,32.42 JP4.3
S_OUT_P: length 41.6
  L6_SIGNAL w0.089: v1(23.55,1.76) 23.29,2.01 23.29,2.63 22.64,3.28 19.46,3.28 19.1,3.64 19.1,5.06 21.13,7.09 21.13,9.89 22.02,10.78 22.02,12.43 19.95,14.5 19.95,23.62 19.33,24.24 18.7,24.24 18.34,24.6 18.34,28.66 17.45,29.55 17.45,30.97 17.71,31.22 17.71,31.35 17.45,31.6 17.45,31.81 17.58,31.93 17.76,31.93 v1(17.96,31.73)
  BOTTOM w0.089: v1(23.55,1.76) 23.25,2.06 23.25,2.46 23.39,2.6 U10.4 ; JP3.3 17.15,31.62 17.43,31.9 17.79,31.9 v1(17.96,31.73)
SCL: length 83.6
  TOP w0.127: U1.W6 v1(21.94,34.59)
  L4_SIGNAL w0.095: v1(37.52,12.3) 37.52,14.33 35.51,16.34 33.98,16.34 33.52,16.81 31.87,16.81 31.1,16.05 26.72,16.05 25.07,17.7 16.5,17.7 15.55,18.65 15.55,33.7 16.56,34.72 20.44,34.72 20.94,34.21 21.58,34.21 21.94,34.56 v1(21.94,34.59)
  L13_SIGNAL w0.095: v1(4.24,18.52) 7.93,22.21 7.93,31.73 10.47,34.27 16.31,34.27 16.94,33.64 19.99,33.64 20.5,34.14 21.52,34.14 21.94,34.56 v1(21.94,34.59)
  BOTTOM w0.14: U21.2 4.31,19.36 R58.2 v1(4.24,18.52) ; JX2.17 37.52,10.97 v1(37.52,12.3)
SCL_AD7291: length 114.6
  TOP w0.14: v1(77.27,47.61) 77.78,47.61 R44.2
  L12_SIGNAL w0.095: v1(6.15,25) 6.91,25 7.42,25.51 7.42,27.79 6.66,28.56 6.02,28.56 5.64,28.94 5.64,29.83 5.26,30.21 5.26,39.73 6.28,40.75 6.28,44.18 9.96,47.86 11.74,47.86 14.14,50.27 15.79,50.27 17.71,52.18 17.71,52.69 20.37,55.35 24.81,55.35 25.81,56.35 29.03,56.35 29.64,55.73 56.57,55.73 59.48,58.65 60.62,58.65 62.03,60.05 65.74,60.05 65.82,60.14 66.11,60.14 66.19,60.05 70.28,60.05 78.03,52.31 78.03,48.37 v1(77.27,47.61)
  BOTTOM w0.14: v1(6.15,25) 5.64,24.49 4.62,24.49 4.31,24.8 U21.7 ; v1(77.27,47.61) 77.13,47.46 U24.15
SD_SEL: length 128.8
  TOP w0.14: v1(10.59,12.43) 10.21,12.81 9.2,12.81 9.05,12.66 U11.24 ; S1.2 v1(4.62,11.71) ; v1(79.94,55.61) 79.94,57 79.43,57.51 U5.5
  L6_SIGNAL w0.095: v1(4.62,11.71) 5.6,12.68 10.34,12.68 v1(10.59,12.43)
  L15_SIGNAL w0.095: v1(79.94,55.61) 37.83,55.61 37.07,54.85 37.07,53.45 36.95,53.32 34.85,53.32 31.93,56.24 25.83,56.24 25.33,56.75 18.53,56.75 11.74,49.96 11.74,27.73 13.07,26.4 14.72,26.4 14.97,26.14 14.97,24.94 10.04,20.01 10.04,19.91 9.84,19.71 9.75,19.71 9.07,19.03 9.07,13.95 v1(10.59,12.43)
SDA: length 86.3
  TOP w0.14: U1.V6 v1(22.74,34.59)
  L4_SIGNAL w0.095: v1(22.74,34.59) 22.34,34.19 22.34,33.58 22.15,33.38 17.45,33.38 15.99,31.92 15.99,18.78 16.69,18.08 25.2,18.08 26.15,17.13 35.8,17.13 36.18,16.75 36.18,16.17 38.47,13.89 38.47,12.55 v1(38.22,12.3)
  L13_SIGNAL w0.095: v1(3.29,19.29) 3.29,18.78 3.99,18.08 4.5,18.08 8.43,22.02 8.43,31.6 10.59,33.76 16.05,33.76 16.82,33 20.5,33 20.88,33.38 22.15,33.38 22.4,33.63 22.4,34.25 v1(22.74,34.59)
  BOTTOM w0.14: R57.2 2.59,19.29 v1(3.29,19.29) 3.29,19.73 3.66,20.1 U21.3 ; JX2.19 38.28,11.01 38.28,12.24 v1(38.22,12.3)
SDA_AD7291: length 113.3
  TOP w0.14: R42.2 76.63,48.74 v1(76.63,47.6)
  L12_SIGNAL w0.095: v1(6.15,23.98) 6.91,23.98 7.8,24.87 7.8,28.18 6.15,29.83 6.15,30.08 5.64,30.59 5.64,39.48 7.8,41.64 7.8,44.18 10.97,47.35 12.12,47.35 14.4,49.64 16.05,49.64 18.34,51.92 18.34,52.43 20.65,54.74 24.35,54.74 24.37,54.72 25.23,54.72 25.86,55.35 56.95,55.35 59.62,58.02 60.89,58.02 61.9,59.04 70.41,59.04 77.01,52.43 77.01,50.63 76.93,50.54 76.93,50.26 77.01,50.17 77.01,49.64 76.63,49.26 76.63,47.61 v1(76.63,47.6)
  BOTTOM w0.14: v1(6.15,23.98) 4.24,23.98 3.66,24.56 U21.6 ; U24.14 v1(76.63,47.6)
SDIO_CLKB0: length 24.6
  TOP w0.14: v1(1.45,28.81) 2.08,28.81 2.54,28.36 J3.5 ; v1(6.15,11.79) 6.55,12.19 U11.19
  L6_SIGNAL w0.095: v1(1.45,28.81) 1.96,28.81 2.37,28.4 2.37,28.34 3.48,27.23 3.48,21.06 2.72,20.3 2.72,18.97 3.23,18.46 3.23,12.49 4.5,11.22 5.58,11.22 v1(6.15,11.79)
SDIO_CLKB1: length 16.8
  TOP w0.14: U11.13 5.41,15.84 5.04,16.2 5.04,16.4 v1(5.64,17)
  L6_SIGNAL w0.095: v1(9.45,28.17) 7.93,26.65 7.93,18.02 6.91,17 v1(5.64,17)
  BOTTOM w0.14: JX3.43 v1(9.45,28.17)
SDIO_CMDB0: length 23.2
  TOP w0.14: v1(6.15,11.09) 7.05,11.99 U11.20 ; J3.3 v1(1.85,26.16)
  L6_SIGNAL w0.095: v1(6.15,11.09) 5.96,10.9 4.31,10.9 2.85,12.36 2.85,17.51 2.34,18.02 2.34,20.56 3.23,21.44 3.23,24.78 v1(1.85,26.16)
  BOTTOM w0.14: v1(6.15,11.09) 5.96,10.9 R109.2
SDIO_CMDB1: length 13.2
  TOP w0.14: v1(5.77,17.76) 6.55,16.98 U11.12
  L15_SIGNAL w0.095: v1(5.77,17.76) 6.28,18.27 7.8,18.27 8.56,19.03 8.56,20.17 10.59,22.21 v1(10.59,23.35)
  BOTTOM w0.14: JX3.34 11.41,24.17 10.8,23.56 10.8,23.56 v1(10.59,23.35) ; v1(5.77,17.76) 4.88,17.76
SDIO_DAT0B0: length 22.2
  TOP w0.14: U11.18 5.15,13.34 v1(4.62,12.81) ; J3.7 v1(1.93,30.56)
  L6_SIGNAL w0.095: v1(1.93,30.56) 1.93,29.48 3.86,27.54 3.86,17.95 4.37,17.44 4.37,16.87 3.61,16.11 3.61,13.82 v1(4.62,12.81)
SDIO_DAT0B1: length 14.5
  TOP w0.14: U11.14 v1(5.14,15.34)
  L6_SIGNAL w0.095: v1(6.79,25.77) 7.55,25.02 7.55,18.78 7.04,18.27 5.77,18.27 5.14,17.65 v1(5.14,15.34)
  BOTTOM w0.14: JX3.37 v1(6.79,25.77)
SDIO_DAT1B0: length 21.6
  TOP w0.14: J3.8 v1(1.93,31.66) ; U11.16 v1(5.14,14.34)
  L6_SIGNAL w0.095: v1(1.93,31.66) 2.59,30.99 2.59,29.45 4.12,27.92 4.12,20.49 4.62,19.98 4.62,16.62 3.99,15.98 3.99,14.71 4.37,14.33 5.13,14.33 v1(5.14,14.34)
SDIO_DAT1B1: length 17.6
  TOP w0.14: U11.15 v1(4.5,14.84)
  L6_SIGNAL w0.095: v1(4.5,14.84) 5.89,14.84 6.28,15.22 7.55,15.22 8.94,16.62 8.94,17.76 10.47,19.29 10.47,21.7 11.36,22.59 11.36,24.59 v1(10.97,24.97)
  BOTTOM w0.14: JX3.36 v1(10.97,24.97)
SDIO_DAT2B0: length 24.6
  TOP w0.14: J3.1 v1(1.86,23.96) ; v1(9.83,10.65) 8.55,11.93 U11.23
  L6_SIGNAL w0.095: v1(1.86,23.96) 1.86,12.91 4.5,10.27 5.89,10.27 6.78,11.16 9.32,11.16 v1(9.83,10.65)
SDIO_DAT2B1: length 12.6
  TOP w0.14: v1(9.7,19.03) 8.94,18.27 8.94,17.63 8.55,17.24 U11.8
  L6_SIGNAL w0.095: v1(9.7,19.03) 10.09,19.41 10.09,23.48 9.07,24.49 9.07,26.14 9.5,26.57 v1(9.53,26.57)
  BOTTOM w0.14: JX3.39 v1(9.53,26.57)
SDIO_DAT3B0: length 26.7
  TOP w0.14: v1(9.07,10.65) 8.05,11.67 U11.22 ; J3.2 v1(1.89,25.06)
  L6_SIGNAL w0.095: v1(1.89,25.06) 1.45,24.62 1.45,12.81 5.64,8.62 7.67,8.62 9.07,10.01 v1(9.07,10.65)
SDIO_DAT3B1: length 13.6
  TOP w0.14: v1(6.66,18.65) 7.04,18.65 7.55,18.14 U11.10
  L15_SIGNAL w0.095: v1(10.34,25) 10.34,24.11 8.18,21.95 8.18,19.29 7.55,18.65 v1(6.66,18.65)
  BOTTOM w0.14: v1(10.34,25) 11.11,25.77 JX3.38
SYNC: length 6.4
  TOP w0.356: 19.1,6.66 19.1,7.31 U18.9 ; 19.1,6.66 19.1,6.01 U18.11 ; 19.1,6.66 U18.10
TX_MON: length 4.7
  TOP w0.394: C6.2 72.65,27.14 arc(72.04,27.21) 71.47,27.44 U17.M5
TX_VCO_1P1V_SUPPLY: length 6
  TOP w0.127: U17.B11 v1(61.2,33.69) ; U17.A11 v1(60.4,33.69)
  BOTTOM w0.14: v1(61.2,33.69) v1(60.4,33.69) 60.33,33.76 60,33.76 59.62,34.14 R123.1 58.98,36.49 C104.2
TXA_N: length 8.7
  TOP w0.267: C25.1 74.07,35.14 73.95,35.01 73.65,35.01 arc(73.29,34.94) 72.99,34.74 72.3,34.06 arc(71.96,33.55) 71.85,32.95 71.85,30.51 arc(71.76,30.31) 71.56,30.23 71.23,30.23 71.12,30.34 L8.2 70.93,30.23 70.62,30.23 70.17,30.68 69.95,30.68 U17.M8
TXA_P: length 8.7
  TOP w0.267: U17.M7 69.66,30.16 69.95,30.16 70.41,29.7 70.94,29.7 L9.2 71.15,29.7 71.56,29.7 arc(72.13,29.94) 72.37,30.51 72.37,32.95 arc(72.45,33.35) 72.67,33.69 73.36,34.37 arc(73.49,34.46) 73.65,34.49 73.95,34.49 74.07,34.37 C26.1
TXB_N: length 11.2
  TOP w0.267: U17.M10 69.63,32.39 arc(69.73,32.25) 69.88,32.2 69.99,32.2 arc(70.28,32.32) 70.4,32.61 70.4,33.64 70.41,34.83 70.41,35.76 L1.2 70.4,35.98 70.41,36.22 arc(70.44,36.63) 70.53,37.02 arc(70.53,37.02) 70.53,37.02 71.07,38.57 arc(71.74,39.47) 72.81,39.8 74.07,39.8 arc(74.22,39.8) C99.1
TXB_P: length 11.2
  TOP w0.267: C110.1 74.25,39.25 arc(74.19,39.27) 74.13,39.28 72.81,39.28 arc(72.04,39.04) 71.56,38.4 71.03,36.86 arc(70.95,36.54) 70.93,36.22 70.93,35.98 L2.2 70.93,35.76 70.93,34.83 70.93,33.64 70.93,32.61 arc(70.65,31.95) 69.99,31.68 69.61,31.68 U17.M9
UNNAMED_2_CAP_I87_N1: length 1.8
  BOTTOM w0.14: C242.1 24.39,12.22 U10.41
UNNAMED_2_CAP_I87_N2: length 1.7
  BOTTOM w0.14: C242.2 22.39,12.42 U10.37
UNNAMED_2_CAP_I153_N1: length 15.4
  TOP w0.14: v1(30.36,12.81) 31.2,11.96 Y2.1
  L4_SIGNAL w0.095: v1(19.99,11.79) 21.2,13 29.71,13 29.9,12.81 v1(30.36,12.81)
  BOTTOM w0.14: C59.1 v1(19.99,11.79) 20.39,11.39 U10.33
UNNAMED_2_CAP_I154_N1: length 22.6
  TOP w0.14: v1(35.61,13.06) 35.23,13.06 34.64,13.66 Y2.3
  L4_SIGNAL w0.095: v1(20.63,11.79) 21.26,12.43 23.17,12.43 23.42,12.17 29.64,12.17 30.21,11.6 35.55,11.6 35.99,12.05 35.99,12.68 v1(35.61,13.06)
  BOTTOM w0.14: C60.1 22.02,13.19 v1(20.63,11.79) 20.89,11.53 U10.34
UNNAMED_2_DIO6PV8_I47_REF1: length 2.5
  TOP w0.14: U16.2 v1(15.55,55.1)
  BOTTOM w0.14: R178.2 v1(15.55,55.1)
UNNAMED_2_IC88E151X_I86_CONFIG: length 2.3
  BOTTOM w0.14: R12.2 16.87,3.84 U10.15
UNNAMED_2_IC88E151X_I86_RSET: length 2.3
  BOTTOM w0.14: U10.30 18.89,11.62 18.59,11.92 18.34,11.92 R50.1
UNNAMED_2_ICUSB3320C_I42_RBIAS: length 2.3
  TOP w0.14: U15.24 19.13,51.19 R176.1
UNNAMED_2_ICUSB3320C_I42_REFCLK: length 4
  TOP w0.14: v1(21.39,49.64) 21.66,49.91 U15.26
  BOTTOM w0.14: v1(21.39,49.64) 21.39,51.2 R175.1
UNNAMED_2_RES_I8_N2: length 25.5
  TOP w0.14: R191.1 44.5,16.05 44.18,16.36 43.93,16.36 ; 43.93,16.36 43.93,16.87 43.68,17.13 42.6,17.13 40.82,18.9 40.06,18.9 38.28,20.68 38.28,29.95 37.64,30.59 33.96,30.59 33.56,30.19 U1.E11 ; 43.93,16.36 43.68,16.36 43.36,16.05 R194.2
UNNAMED_2_RES_I50_N2: length 5.5
  TOP w0.14: v1(19.61,56.24) 18.46,56.24 Y3.3
  BOTTOM w0.14: v1(19.61,56.24) 20.88,56.24 21.39,55.73 21.39,54.85 22.32,53.92 R175.2
UNNAMED_2_RES_I105_N1: length 2.7
  TOP w0.14: Q4.3 3.86,52.53 R18.1
UNNAMED_2_RES_I108_N2: length 8.1
  TOP w0.14: Q4.1 6.22,51.62 7.24,52.64 7.24,55.3 R16.2 9.07,57.13 Q2.3
UNNAMED_2_RES_I112_N1: length 1.7
  TOP w0.14: R17.1 Q3.3
UNNAMED_2_RES_I114_N2: length 7.2
  TOP w0.14: R15.2 32.95,6.59 33.58,7.22 34.98,7.22 35.99,8.24 35.99,9.02 Q1.3 37.52,9.13 38.1,8.54 Q3.1
UNNAMED_3_ICMT25Q_I231_RESET: length 8.2
  TOP w0.14: v1(68.89,48.5) 68.89,51.67 69.15,51.94 69.15,53.84 69.23,53.92 69.23,55.23 U13.A4
  BOTTOM w0.14: R19.2 v1(68.89,48.5)
UNNAMED_3_ICXC7Z20_I217_PSCLK50: length 43.5
  TOP w0.127: U1.E7 v1(33.94,33.79)
  TOP w0.14: R114.2 v1(46.03,12.94)
  L12_SIGNAL w0.095: v1(27.1,20.81) 27.1,19.54 28.88,17.76 29.26,17.76 31.21,15.81 34.61,15.81 34.81,15.62 34.81,15.32 35.08,15.05 35.08,14.49 37.18,12.39 37.18,12.16 37.42,11.92 41.94,11.92 42.95,12.94 v1(46.03,12.94)
  L16_SIGNAL w0.095: v1(33.94,33.79) 33.61,33.79 33.15,33.33 32.99,33.33 32.8,33.13 32.8,32.97 32.35,32.53 31.39,32.53 31.2,32.33 31.2,32.14 30.78,31.73 30.59,31.73 30.4,31.53 30.4,31.34 28.38,29.33 28.19,29.33 28,29.13 28,28.94 27.99,28.94 27.99,22.33 27.1,21.44 v1(27.1,20.81)
UNNAMED_3_RES_I30_N2: length 16.3
  TOP w0.14: S3.2 52.88,55.23 53.27,54.85 54.92,54.85 56.57,53.19 60.12,53.19 v1(64.06,49.26)
  BOTTOM w0.14: R121.2 v1(64.06,49.26)
UNNAMED_3_RES_I33_N2: length 16.2
  TOP w0.14: v1(47.93,56.88) 47.47,56.41 S4.2
  L4_SIGNAL w0.095: v1(61.52,57.51) 60.63,56.62 48.69,56.62 48.44,56.88 v1(47.93,56.88)
  BOTTOM w0.14: 62.28,57.51 v1(61.52,57.51)
UNNAMED_3_RES_I222_N1: length 2.2
  TOP w0.14: Y1.3 45.91,7.72 45.91,9.43 R114.1
UNNAMED_3_RES_I228_N2: length 4.4
  TOP w0.14: Y1.1 v1(47.58,4.84)
  BOTTOM w0.14: v1(47.58,4.84) 46.92,4.17 R41.1 R40.2
UNNAMED_5_ICMT41K256M16_I128_ZQ: length 4.2
  TOP w0.14: v1(48.83,26.7) 49.2,26.33 49.78,26.33 50.21,25.89 50.98,25.89 51.74,26.65 R165.1
  BOTTOM w0.14: v1(48.83,26.7) 48.76,26.7 U2.L8
UNNAMED_5_ICMT41K256M16_I137_ZQ: length 3.4
  TOP w0.14: R166.1 50.84,43.03 50.32,43.55 48.82,43.55 v1(48.78,43.59)
  BOTTOM w0.14: v1(48.78,43.59) 48.78,43.58 48.78,43.48 U3.L8
UNNAMED_5_ICTPS51206_I120_S3: length 4
  BOTTOM w0.14: R222.2 43.23,58.4 43.42,58.21 45.01,58.21 45.2,58.4 45.2,58.85 45.37,59.02 U14.7
UNNAMED_5_ICTPS51206_I120_S5: length 1.9
  BOTTOM w0.203: 45.16,59.82 U14.9
  BOTTOM w0.254: R221.2 45.16,59.82
UNNAMED_5_ICTPS51206_I120_VLDOI: length 2
  BOTTOM w0.203: U14.2 48.46,59.82
  BOTTOM w0.254: 48.46,59.82 R6.2
UNNAMED_5_ICTPS51206_I120_VTTSN: length 1.9
  BOTTOM w0.14: U14.5 48.22,58.62 48.57,58.27 R161.2
UNNAMED_5_ICXC7Z20_I195_PSDDR_2: length 7.9
  TOP w0.127: U1.H5 v1(31.54,35.39)
  BOTTOM w0.14: R135.1 33.83,40.88 31.93,38.97 31.93,35.78 v1(31.54,35.39)
UNNAMED_5_ICXC7Z20_I195_PSDDRVR: length 17.6
  TOP w0.127: U1.G5 v1(32.34,35.39)
  TOP w0.14: v1(38.72,48.75) 39.55,48.75 R134.1
  L3_SIGNAL w0.095: v1(38.72,48.75) 34.22,44.24 34.22,41 32.69,39.48 32.69,35.8 32.34,35.44 v1(32.34,35.39)
UNNAMED_6_CAP_I20_N1: length 18.4
  TOP w0.127: U1.G8 v1(32.34,32.99)
  TOP w0.14: C178.1 v1(36.5,45.07) L12.2
  L3_SIGNAL w0.095: v1(36.5,45.07) 35.49,44.05 35.49,41 33.58,39.1 33.58,33.64 33.33,33.38 32.69,33.38 32.34,33.03 v1(32.34,32.99)
  BOTTOM w0.14: v1(36.5,45.07) C178.1 37.52,45.32 C251.1
UNNAMED_6_CAP_I222_N1: length 20.8
  TOP w0.127: U1.J9 v1(30.74,32.19)
  TOP w0.14: E1.2 28.06,48.18 28.88,47.35 C189.1 C190.1 32.06,46.72 v1(32.18,46.59)
  L3_SIGNAL w0.095: v1(30.74,32.19) 30.74,32.29 31.17,32.72 31.17,44.69 32.18,45.7 v1(32.18,46.59)
UNNAMED_6_CAP_I222_N2: length 27.1
  TOP w0.102: U1.K10 v1(29.94,31.39) ; U1.J10 v1(30.74,31.39)
  TOP w0.127: U1.L9 v1(28.34,32.19)
  TOP w0.305: C190.2 C189.2 29.9,49.51 v1(29.77,49.64) 29.77,50.02 29.33,50.46 E12.2
  L3_SIGNAL w0.102: v1(29.77,49.64) 28.88,48.75 28.88,41.26 29.14,41 29.14,39.73 28.88,39.48 28.88,32.73 v1(28.34,32.19) 29.14,31.39 v1(29.94,31.39) v1(30.74,31.39)
UNNAMED_6_DIOLED_I352_N: length 2.2
  TOP w0.14: 36.63,50.53 D4.C
UNNAMED_6_ICXC7Z20_I344_CFGBVS0: length 20.7
  TOP w0.127: U1.M6 v1(27.54,34.59)
  TOP w0.14: v1(33.83,46.34) 34.09,46.59 R167.2
  L3_SIGNAL w0.095: v1(27.54,34.59) 27.54,34.6 27.1,35.03 27.1,40.49 27.99,41.38 27.99,43.92 27.48,44.43 27.48,45.57 v1(28.37,46.46)
  L7_SIGNAL w0.095: v1(33.83,46.34) 33.07,47.1 30.79,47.1 30.15,46.46 v1(28.37,46.46)
UNNAMED_6_ICXC7Z20_I344_PROGRAM: length 10.6
  TOP w0.14: R169.1 31.29,39.22 29.77,39.22 29.14,38.59 29.14,34.59 U1.L6
UNNAMED_8_AD9364_I22_RBIAS: length 0.9
  TOP w0.127: U17.L4 v1(69.2,27.29)
  BOTTOM w0.14: R125.1 69.33,27.43 v1(69.2,27.29)
UNNAMED_8_CAP_I135_N1: length 1.5
  TOP w0.267: T1.6 C8.1
UNNAMED_8_CAP_I136_N1: length 1.5
  TOP w0.267: T1.4 C9.1
UNNAMED_8_CAP_I200_N1: length 0.8
  TOP w0.394: R1.2 74.56,27.45
UNNAMED_8_CAP_I209_N2: length 1.5
  TOP w0.267: T2.6 C25.2
UNNAMED_8_CAP_I210_N2: length 1.5
  TOP w0.267: T2.4 C26.2
UNNAMED_8_CAP_I395_N2: length 1.2
  TOP w0.14: R2.2 61.9,21.19 C12.2
UNNAMED_8_CAP_I409_N2: length 1.6
  TOP w0.267: T4.6 75.53,41.43 74.39,40.46 C99.2
UNNAMED_8_CAP_I410_N2: length 1.5
  TOP w0.267: 75.09,38.92 75.16,38.95 T4.4
UNNAMED_8_CAP_I416_N1: length 1.6
  TOP w0.267: T3.6 C85.1
UNNAMED_8_CAP_I417_N1: length 1.6
  TOP w0.267: C90.1 66.88,19.29 68.06,19.29 T3.4
UNNAMED_8_CAP_I425_N2: length 1.2
  BOTTOM w0.14: R123.2 59.55,37.19 58.73,37.19 58.6,37.32 C105.2
UNNAMED_8_CNBNC3P_I358_CNTR: length 15.5
  TOP w0.394: RXA.1 86.79,26.52 arc(85.58,26.36) 84.45,25.89 84.43,25.88 arc(83.74,25.6) 83,25.51 80.95,25.51 arc(80.76,25.49) 80.59,25.42 79.74,24.95 T1.3
UNNAMED_8_CNBNC3P_I359_CNTR: length 16.5
  TOP w0.394: TXA.1 93.17,37.95 arc(92.16,37.87) 91.18,37.64 80.29,33.48 T2.3
UNNAMED_8_CNBNC3P_I360_CNTR: length 16
  TOP w0.394: TXM.1 88.57,32.24 arc(88.16,32.16) 87.81,31.93 84.86,28.97 arc(83.84,28.29) 82.63,28.05 81.04,28.05 arc(80.61,28.13) 80.24,28.38 arc(79.59,28.81) 78.83,28.96 78.15,28.96 arc(77.27,28.85) 76.44,28.54 R1.1
UNNAMED_8_CNBNC3P_I404_CNTR: length 18.1
  TOP w0.394: TXB.1 94.21,49.38 arc(92.09,49.05) 90.19,48.06 80.5,40.98 T4.3
UNNAMED_8_CNBNC3P_I421_CNTR: length 24
  TOP w0.394: RXB.1 94.29,15.09 arc(93.17,15.2) 92.1,15.52 83.2,18.46 arc(81.44,18.89) 79.64,19.03 T3.3
UNNAMED_8_ICFXL4T245_I328_T: length 1.8
  TOP w0.14: U22.6 58.33,32.48 58.73,32.87 v1(58.73,32.91)
  BOTTOM w0.14: R59.1 v1(58.73,32.91)
UNNAMED_9_ADP1754_I1076_SS: length 2.2
  TOP w0.14: U19.7 82.42,9.32 82.98,9.89 82.98,10.59 C311.1
UNNAMED_9_ADP1754_I1374_SS: length 1.5
  TOP w0.14: U20.7 93.01,9.32 C340.1
UNNAMED_9_ADP2114_I1272_FREQ: length 2.4
  TOP w0.14: U4.3 66.23,1.64 66.09,1.51 v1(66.09,1)
  BOTTOM w0.14: R10.2 66.09,1.82 v1(66.09,1)
UNNAMED_9_ADP2114_I1272_OPCFG: length 2
  TOP w0.14: v1(67.62,1.31) 67.62,1.57 67.73,1.68 U4.6
  BOTTOM w0.14: v1(67.62,1.31) R20.2
UNNAMED_9_ADP2114_I1272_SS1: length 3.2
  TOP w0.14: U4.30 62.09,3.98 C142.2
UNNAMED_9_ADP2114_I1272_SS2: length 4
  TOP w0.14: C144.2 70.92,3.41 70.35,3.98 U4.11
UNNAMED_9_ADP2114_I1272_SW3: length 0.8
  TOP w0.14: 68.23,7.13 U4.18 68.23,7.58 68.51,7.86
UNNAMED_9_ADP2164_I831_PVIN1: length 24.5
  TOP w0.305: 21.81,3.58 U18.13 21.81,4.46 21.68,4.59 v1(21.26,4.59) v1(20.75,4.59) 20.75,5.3 U18.12 ; v1(27.99,5.95) 27.93,6.01 R304.2 27.36,5.81 R301.2
  TOP w0.406: 21.81,3.58 21.26,3.03 19.93,3.03 C66.1
  TOP w0.508: 32.69,2.52 32.18,3.03 v1(31.68,3.03) ; 32.69,2.52 32.56,2.52 32.18,2.14 v1(31.68,2.14) ; 32.69,2.52 L302.2
  L4_SIGNAL w0.406: v1(31.68,2.14) v1(31.68,3.03) 30.15,4.55 28.63,4.55 27.99,5.19 ; v1(20.75,4.59) v1(21.26,4.59) 21.48,4.81 24.82,4.81 25.2,5.19 27.99,5.19 ; v1(27.99,5.95) 27.99,5.19
UNNAMED_9_ADP2164_I831_RT: length 7.2
  TOP w0.14: v1(26.34,5.95) 26.29,6.01 U18.2 ; v1(27.54,10.01) 27.48,9.96 27.48,9.89 26.98,9.38 R38.1
  L6_SIGNAL w0.095: v1(27.54,10.01) 27.54,9.68 26.34,8.49 v1(26.34,5.95)
UNNAMED_9_ADP2164_I831_SYNC: length 14.7
  TOP w0.14: 25.45,5.36 25.45,5.27 25.45,4.68 ; 25.45,5.36 U18.1 ; 25.45,5.36 26.51,5.36 26.72,5.57 26.72,6.09 26.59,6.22 26.59,6.46 26.39,6.66 U18.3 ; 25.45,4.68 26.34,4.68 26.45,4.79 26.87,4.79 26.92,4.74 R301.1 ; 25.45,4.68 25.45,3.66 ; U18.14 22.46,3.74 22.91,3.28 25.07,3.28 25.45,3.66 ; 25.45,3.66 26.21,3.66 26.47,3.41 C61.1
UNNAMED_9_CAP_I1394_N1: length 0.4
  BOTTOM w0.406: v2(15.04,8.36) C127.1
UNNAMED_9_CAP_I1398_N2: length 24.9
  TOP w0.406: R49.1 8.56,1.12 v2(7.04,2.65) ; R48.2 v2(20.16,9.67)
  L4_SIGNAL w0.406: v2(20.16,9.67) 20.16,10.36 19.61,10.9 18.21,10.9 17.71,10.4 15.42,10.4 14.28,9.25 13.01,9.25 v2(11.99,8.24) 11.99,7.6 v2(7.04,2.65)
  BOTTOM w0.406: v2(11.99,8.24) 11.99,8.74 13.01,9.76 14.78,9.76 C127.2
UNNAMED_9_CAP_I1416_N2: length 1.3
  BOTTOM w0.14: R47.1 C114.2
UNNAMED_9_CAP_I1449_N1: length 1.3
  BOTTOM w0.14: C69.1 R46.2
UNNAMED_9_DIOLED_I1180_N: length 1.8
  TOP w0.14: D3.C 31.55,56.5 31.04,55.99 R113.1
UNNAMED_9_RES_I987_N2: length 2.1
  TOP w0.14: 32.31,54.97 Q14.3
UNNAMED_10_AD7291_I1_AS0: length 2.1
  BOTTOM w0.14: R66.1 R65.2 75.13,48.19 U24.11
UNNAMED_10_AD7291_I1_AS1: length 2.1
  BOTTOM w0.14: U24.13 76.13,48.18 R63.2 R64.1
UNNAMED_10_AD7291_I1_DCAP: length 1.5
  BOTTOM w0.14: C133.1 U24.8
UNNAMED_10_AD7291_I1_VIN3: length 3.7
  BOTTOM w0.14: U24.1 77.13,41.27 77.65,40.75 R68.1 R67.2
UNNAMED_10_AD7291_I1_VIN6: length 3.1
  BOTTOM w0.305: U24.4 75.63,42.28 74.98,41.64 R61.2 R62.1
UNNAMED_10_AD7291_I1_VREF: length 2.8
  BOTTOM w0.14: C158.1 72.4,44.05 73.2,44.05 73.59,44.44 U24.7
UNNAMED_10_ADG772_I53_D1: length 31.8
  TOP w0.14: U5.2 78.08,56.17 77.14,55.23 73.71,55.23 v1(72.82,56.12)
  L16_SIGNAL w0.095: v1(72.82,56.12) 73.71,55.23 74.22,55.23 76.76,52.69 76.76,50.27 77.01,50.02 77.01,49.77 74.09,46.84 74.09,43.06 73.88,42.84 72.76,42.84 v1(72.32,42.4)
  BOTTOM w0.14: C216.1 71.1,36.71 71.1,41.18 v1(72.32,42.4)
UNNAMED_10_ADG772_I53_IN1: length 4.8
  TOP w0.14: v1(79.43,56.24) 79.43,56.88 79.19,57.11 U5.4 ; v1(80.57,56.62) R33.2 80.63,57.26 Q6.3
  BOTTOM w0.14: v1(79.43,56.24) 80.19,56.24 v1(80.57,56.62)
UNNAMED_10_ADG772_I53_S1A: length 1.8
  TOP w0.14: C62.2 76.44,57 76.78,57 76.89,57.11 U5.1
UNNAMED_10_ADG772_I53_S1B: length 5.1
  TOP w0.14: U5.3 78.48,55.3 78.03,54.85 76.63,54.85 75.68,53.9 Y4.3
UNNAMED_10_ADM7160_I65_VOUT: length 5.1
  BOTTOM w0.14: v1(74.77,51.77) 75.46,51.77 75.49,51.8 R55.1
  BOTTOM w0.305: R55.1 76.34,52.52 78.25,52.52 78.86,53.13 U7.5
  vias: v1(74.09,51.29) v1(74.6,51.29)
